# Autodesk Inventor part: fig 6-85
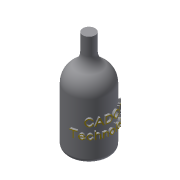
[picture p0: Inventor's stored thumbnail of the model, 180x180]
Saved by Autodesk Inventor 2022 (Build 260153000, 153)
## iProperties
Part Number: fig 6-85
Document SubType Name: Modeling
Created: 2002-12
Designer: deepak
Density: 1 g/cm^3
Material: Generic
Appearance: Default
Control State: 0
Master: False
Checked Out: False
Shininess: 64.0
Length Units: 11269
Angle Units: 11279
Time Units: 11290
Mass Units: 11283
Length Display Precision: 3
Angle Display Precision: 2
Compacted: True
Density: 0.0
Volumn: 0.0
Area: 0.0
PropertySet Name: Model Information
Author: deepak
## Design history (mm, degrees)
node "Sketch1"
sketch "Sketch2"
  geometry: L1 (-7.653, 24.992)-(-7.653, 16.776); L2 (-14.653, 3.659)-(-14.653, -3.57); L3 (-14.653, -3.57)-(-14.653, -23.329); L4 (-14.653, -23.329)-(-4.653, -23.329); L5 (-4.653, -23.329)-(-4.653, 24.992); L6 (-4.653, 24.992)-(-7.653, 24.992); A1 r 6.757 centre (-14.41, 16.776) between (-10.649, 11.163) and (-7.653, 16.776); A2 r 9.033 centre (-5.62, 3.659) between (-10.649, 11.163) and (-14.653, 3.659)
  constraints: 12 end point, 4 point on circle, 3 tangent, 2 centre point, 2 parallel, 2 perpendicular, 1 collinear, 1 vertical
  dimensions: "d0" = 3 distance of L5.end L1.start; "d1" = 10 distance of L3.end L4.end
revolve "Revolution1" sketch "Sketch2" stored, may be unused: angle "d2" = 90 deg
fillet "Fillet1" dims "d3" = 2
workplane "Work Plane1"
workplane "Work Plane2"
sketch "Sketch3"
  geometry: L1 (-24.815, -3.793)-(24.913, -3.793); L2 (24.913, -3.793)-(24.913, -8.382); L3 (24.913, -8.382)-(-24.815, -8.382); L4 (-24.815, -8.382)-(-24.815, -3.793)
  constraints: 2 other
emboss "Emboss1" sketch "Sketch3" dims "d5" = 1, "d6" = 0
body "Solid1"
other parameters: "d4" = 3.5
